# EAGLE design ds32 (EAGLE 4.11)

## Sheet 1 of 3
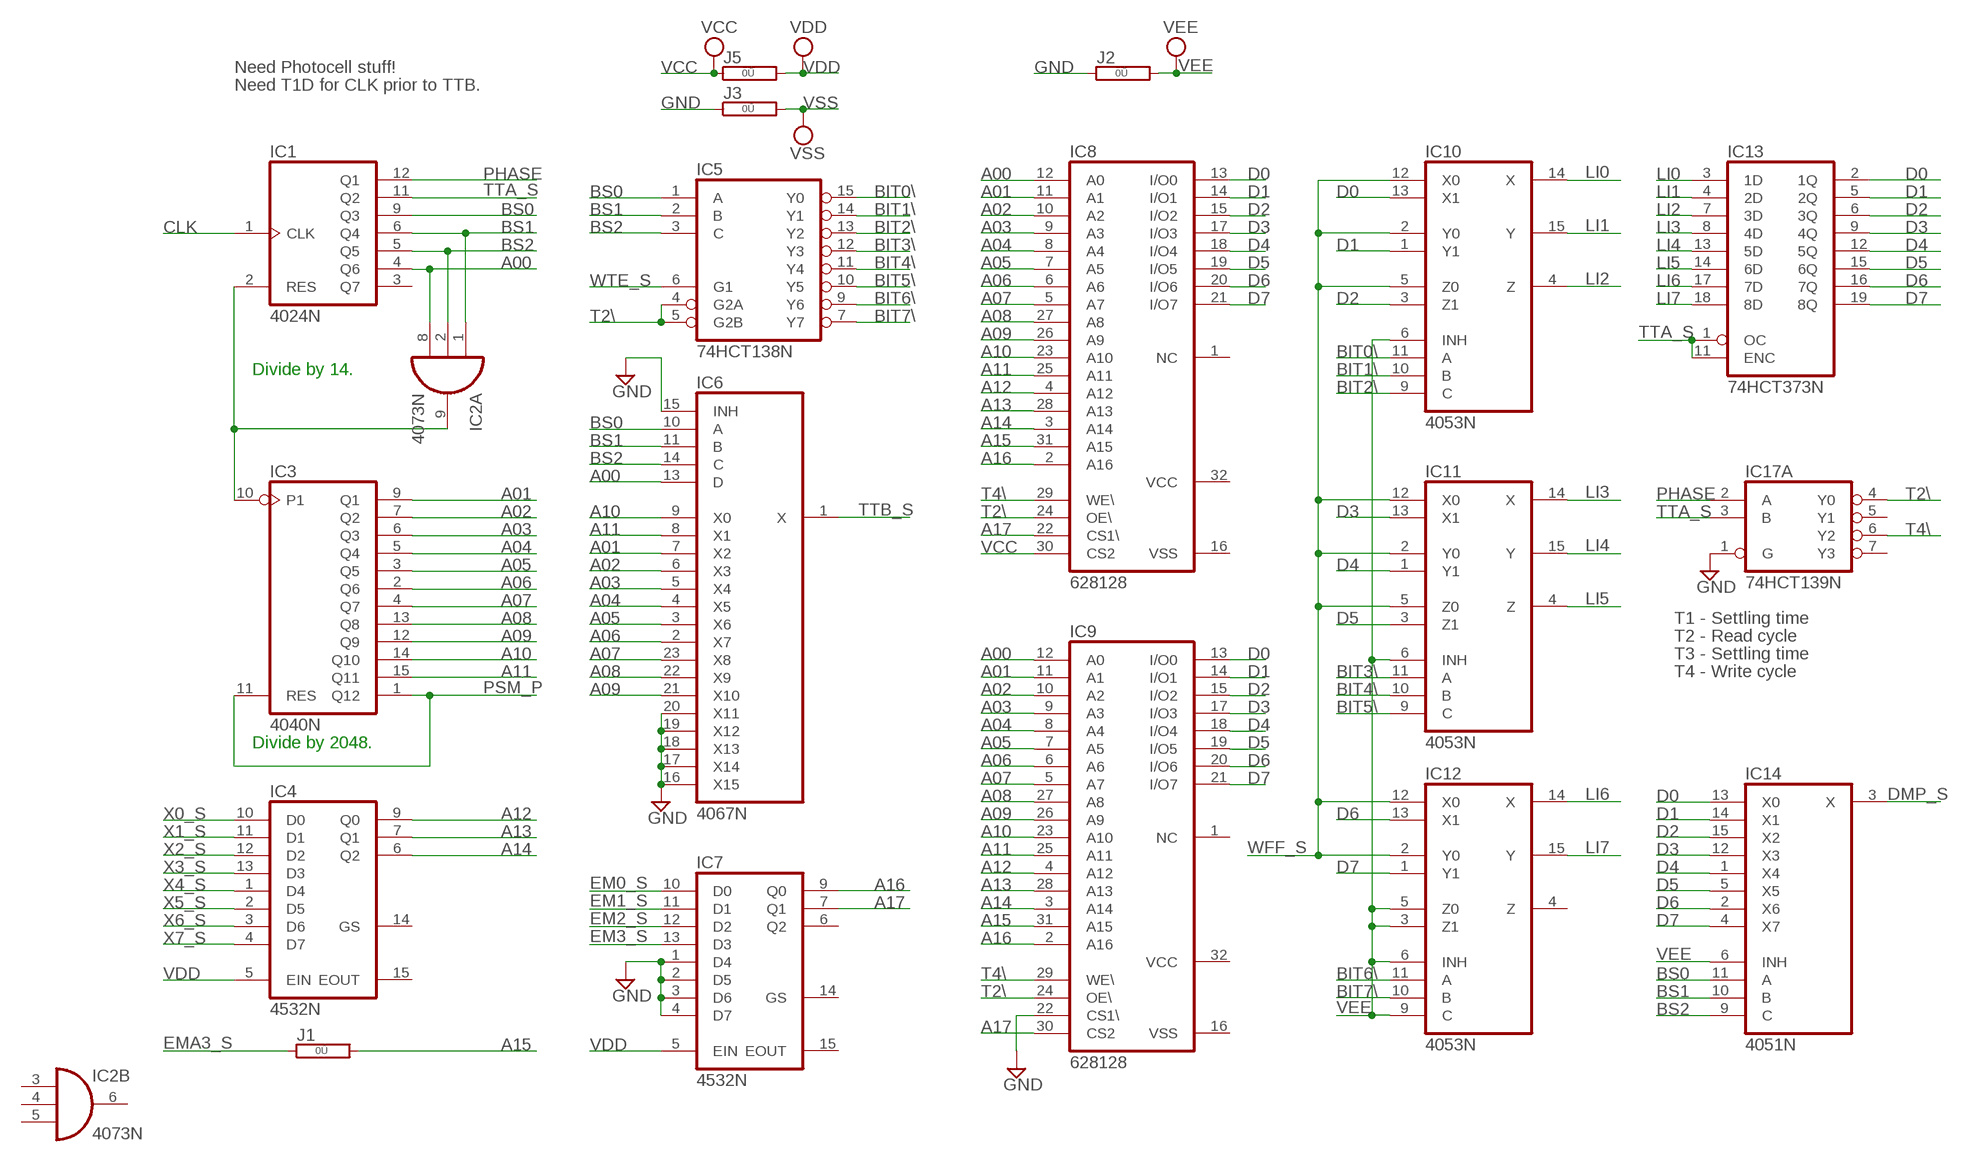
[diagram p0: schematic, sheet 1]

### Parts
IC1  4024N  [DIL14]
IC2  4073N  [DIL14]
IC3  4040N  [DIL16]
IC4  4532N  [DIL16]
IC5  74HCT138N  74LS138N  [DIL16]
IC6  4067N  [DIL24-6]
IC7  4532N  [DIL16]
IC8  628128  628128P  [DIL32]
IC9  628128  628128P  [DIL32]
IC10  4053N  [DIL16]
IC11  4053N  [DIL16]
IC12  4053N  [DIL16]
IC13  74HCT373N  74LS373N  [DIL20]
IC14  4051N  [DIL16]
IC17  74HCT139N  74LS139N  [DIL16]
J1  0R  [0R/10]
J2  0R  [0R/10]
J3  0R  [0R/10]
J5  0R  [0R/10]

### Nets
A00: IC1.4(Q6) IC2.8(A:I2) IC6.13(D) IC8.12(A0) IC9.12(A0)
A01: IC3.9(Q1) IC6.7(X2) IC8.11(A1) IC9.11(A1)
A02: IC3.7(Q2) IC6.6(X3) IC8.10(A2) IC9.10(A2)
A03: IC3.6(Q3) IC6.5(X4) IC8.9(A3) IC9.9(A3)
A04: IC3.5(Q4) IC6.4(X5) IC8.8(A4) IC9.8(A4)
A05: IC3.3(Q5) IC6.3(X6) IC8.7(A5) IC9.7(A5)
A06: IC3.2(Q6) IC6.2(X7) IC8.6(A6) IC9.6(A6)
A07: IC3.4(Q7) IC6.23(X8) IC8.5(A7) IC9.5(A7)
A08: IC3.13(Q8) IC6.22(X9) IC8.27(A8) IC9.27(A8)
A09: IC3.12(Q9) IC6.21(X10) IC8.26(A9) IC9.26(A9)
A10: IC3.14(Q10) IC6.9(X0) IC8.23(A10) IC9.23(A10)
A11: IC3.15(Q11) IC6.8(X1) IC8.25(A11) IC9.25(A11)
A12: IC4.9(Q0) IC8.4(A12) IC9.4(A12)
A13: IC4.7(Q1) IC8.28(A13) IC9.28(A13)
A14: IC4.6(Q2) IC8.3(A14) IC9.3(A14)
A15: IC8.31(A15) IC9.31(A15) J1.2
A16: IC7.9(Q0) IC8.2(A16) IC9.2(A16)
A17: IC7.7(Q1) IC8.22(CS1\) IC9.30(CS2)
BIT0\: IC5.15(Y0) IC10.11(A)
BIT1\: IC5.14(Y1) IC10.10(B)
BIT2\: IC5.13(Y2) IC10.9(C)
BIT3\: IC5.12(Y3) IC11.11(A)
BIT4\: IC5.11(Y4) IC11.10(B)
BIT5\: IC5.10(Y5) IC11.9(C)
BIT6\: IC5.9(Y6) IC12.11(A)
BIT7\: IC5.7(Y7) IC12.10(B)
BS0: IC1.9(Q3) IC5.1(A) IC6.10(A) IC14.11(A)
BS1: IC1.6(Q4) IC2.1(A:I0) IC5.2(B) IC6.11(B) IC14.10(B)
BS2: IC1.5(Q5) IC2.2(A:I1) IC5.3(C) IC6.14(C) IC14.9(C)
CLK: IC1.1(CLK) ; also sheet 3
D0: IC8.13(I/O0) IC9.13(I/O0) IC10.13(X1) IC13.2(1Q) IC14.13(X0)
D1: IC8.14(I/O1) IC9.14(I/O1) IC10.1(Y1) IC13.5(2Q) IC14.14(X1)
D2: IC8.15(I/O2) IC9.15(I/O2) IC10.3(Z1) IC13.6(3Q) IC14.15(X2)
D3: IC8.17(I/O3) IC9.17(I/O3) IC11.13(X1) IC13.9(4Q) IC14.12(X3)
D4: IC8.18(I/O4) IC9.18(I/O4) IC11.1(Y1) IC13.12(5Q) IC14.1(X4)
D5: IC8.19(I/O5) IC9.19(I/O5) IC11.3(Z1) IC13.15(6Q) IC14.5(X5)
D6: IC8.20(I/O6) IC9.20(I/O6) IC12.13(X1) IC13.16(7Q) IC14.2(X6)
D7: IC8.21(I/O7) IC9.21(I/O7) IC12.1(Y1) IC13.19(8Q) IC14.4(X7)
DMP_S: IC14.3(X) ; also sheet 2
EM0_S: IC7.10(D0) ; also sheet 2
EM1_S: IC7.11(D1) ; also sheet 2
EM2_S: IC7.12(D2) ; also sheet 2
EM3_S: IC7.13(D3) ; also sheet 2
EMA3_S: J1.1 ; also sheet 2
GND [Supply]: IC6.15(INH) IC6.16(X15) IC6.17(X14) IC6.18(X13) IC6.19(X12) IC6.20(X11) IC7.1(D4) IC7.2(D5) IC7.3(D6) IC7.4(D7) IC9.22(CS1\) IC17.1(A:G) J2.1 J3.1 ; also sheet 2,3
LI0: IC10.14(X) IC13.3(1D)
LI1: IC10.15(Y) IC13.4(2D)
LI2: IC10.4(Z) IC13.7(3D)
LI3: IC11.14(X) IC13.8(4D)
LI4: IC11.15(Y) IC13.13(5D)
LI5: IC11.4(Z) IC13.14(6D)
LI6: IC12.14(X) IC13.17(7D)
LI7: IC12.15(Y) IC13.18(8D)
N$1: IC1.2(RES) IC2.9(A:O) IC3.10(P1)
PHASE: IC1.12(Q1) IC17.2(A:A)
PSM_P: IC3.1(Q12) IC3.11(RES) ; also sheet 3
T2\: IC5.4(G2A) IC5.5(G2B) IC8.24(OE\) IC9.24(OE\) IC17.4(A:Y0)
T4\: IC8.29(WE\) IC9.29(WE\) IC17.6(A:Y2)
TTA_S: IC1.11(Q2) IC13.1(OC) IC13.11(ENC) IC17.3(A:B) ; also sheet 2
TTB_S: IC6.1(X) ; also sheet 2
VCC [Supply]: IC8.30(CS2) J5.1 ; also sheet 2,3
VDD [Supply]: IC4.5(EIN) IC7.5(EIN) J5.2
VEE: IC10.6(INH) IC11.6(INH) IC12.3(Z1) IC12.5(Z0) IC12.6(INH) IC12.9(C) IC14.6(INH) J2.2
VSS [Supply]: J3.2
WFF_S: IC10.2(Y0) IC10.5(Z0) IC10.12(X0) IC11.2(Y0) IC11.5(Z0) IC11.12(X0) IC12.2(Y0) IC12.12(X0) ; also sheet 2
WTE_S: IC5.6(G1) ; also sheet 2
X0_S: IC4.10(D0) ; also sheet 2
X1_S: IC4.11(D1) ; also sheet 2
X2_S: IC4.12(D2) ; also sheet 2
X3_S: IC4.13(D3) ; also sheet 2
X4_S: IC4.1(D4) ; also sheet 2
X5_S: IC4.2(D5) ; also sheet 2
X6_S: IC4.3(D6) ; also sheet 2
X7_S: IC4.4(D7) ; also sheet 2
Unconnected: IC1.3(Q7) IC2.10(C:O) IC2.11(C:I0) IC2.12(C:I1) IC2.13(C:I2) IC4.14(GS) IC4.15(EOUT) IC7.6(Q2) IC7.14(GS) IC7.15(EOUT) IC8.1(NC) IC9.1(NC) IC12.4(Z) IC17.5(A:Y1) IC17.7(A:Y3) IC17.9(B:Y3) IC17.10(B:Y2) IC17.11(B:Y1) IC17.12(B:Y0) IC17.13(B:B) IC17.14(B:A) IC17.15(B:G)

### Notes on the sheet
- Need Photocell stuff!
- Need T1D for CLK prior to TTB.
- Divide by 14.
- T1 - Settling time
- T2 - Read cycle
- T3 - Settling time
- T4 - Write cycle
- Divide by 2048.

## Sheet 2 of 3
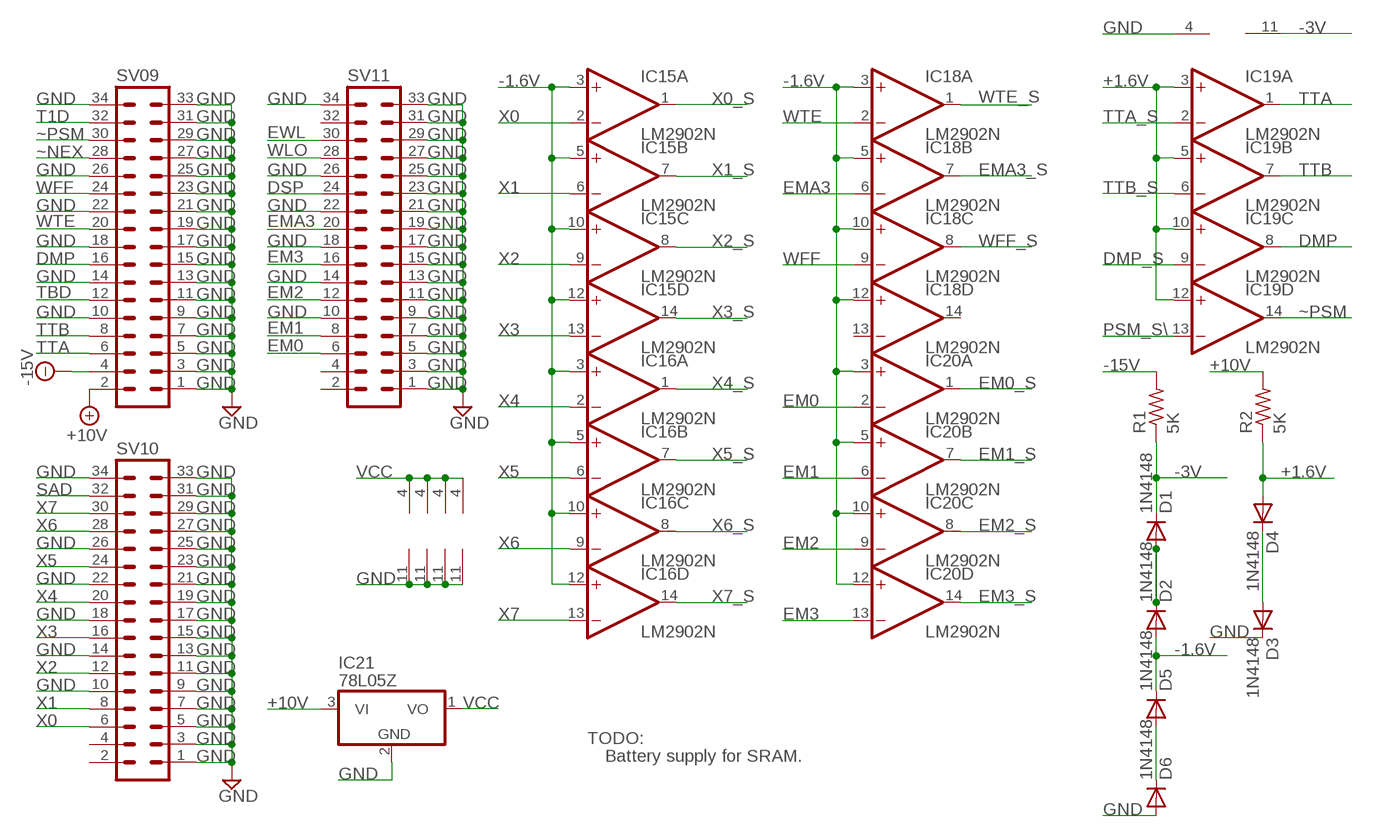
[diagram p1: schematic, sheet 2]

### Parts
D1  1N4148  [DO35-10]
D2  1N4148  [DO35-10]
D3  1N4148  [DO35-10]
D4  1N4148  [DO35-10]
D5  1N4148  [DO35-10]
D6  1N4148  [DO35-10]
IC15  LM2902N  [DIL14]
IC16  LM2902N  [DIL14]
IC18  LM2902N  [DIL14]
IC19  LM2902N  [DIL14]
IC20  LM2902N  [DIL14]
IC21  78L05Z  [TO92]
R1  5K  R-US_0207/10  [0207/10]
R2  5K  R-US_0207/10  [0207/10]
SV09  MA17-2  [MA17-2]
SV10  MA17-2  [MA17-2]
SV11  MA17-2  [MA17-2]

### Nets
+1.6V [Supply]: D4.A IC19.3(A:+IN) IC19.5(B:+IN) IC19.10(C:+IN) IC19.12(D:+IN) R2.1
+10V: IC21.3(VI) R2.2 SV09.2
-1.6V [Supply]: D2.A D5.C IC15.3(A:+IN) IC15.5(B:+IN) IC15.10(C:+IN) IC15.12(D:+IN) IC16.3(A:+IN) IC16.5(B:+IN) IC16.10(C:+IN) IC16.12(D:+IN) IC18.3(A:+IN) IC18.5(B:+IN) IC18.10(C:+IN) IC18.12(D:+IN) IC20.3(A:+IN) IC20.5(B:+IN) IC20.10(C:+IN) IC20.12(D:+IN)
-3V [Supply]: D1.C IC19.11(P:V-) R1.1 ; also sheet 3
-15V: R1.2 SV09.4
DMP: IC19.8(C:OUT) SV09.16
DMP_S: IC19.9(C:-IN) ; also sheet 1
DSP: SV11.24
EM0: IC20.2(A:-IN) SV11.6
EM0_S: IC20.1(A:OUT) ; also sheet 1
EM1: IC20.6(B:-IN) SV11.8
EM1_S: IC20.7(B:OUT) ; also sheet 1
EM2: IC20.9(C:-IN) SV11.12
EM2_S: IC20.8(C:OUT) ; also sheet 1
EM3: IC20.13(D:-IN) SV11.16
EM3_S: IC20.14(D:OUT) ; also sheet 1
EMA3: IC18.6(B:-IN) SV11.20
EMA3_S: IC18.7(B:OUT) ; also sheet 1
EWL: SV11.30
GND [Supply]: D3.C D6.A IC15.11(P:V-) IC16.11(P:V-) IC18.11(P:V-) IC19.4(P:V+) IC20.11(P:V-) IC21.2(GND) SV09.1 SV09.3 SV09.5 SV09.7 SV09.9 SV09.10 SV09.11 SV09.13 SV09.14 SV09.15 SV09.17 SV09.18 SV09.19 SV09.21 SV09.22 SV09.23 SV09.25 SV09.26 SV09.27 SV09.29 SV09.31 SV09.33 SV09.34 SV10.1 SV10.3 SV10.5 SV10.7 SV10.9 SV10.10 SV10.11 SV10.13 SV10.14 SV10.15 SV10.17 SV10.18 SV10.19 SV10.21 SV10.22 SV10.23 SV10.25 SV10.26 SV10.27 SV10.29 SV10.31 SV10.33 SV10.34 SV11.1 SV11.3 SV11.5 SV11.7 SV11.9 SV11.10 SV11.11 SV11.13 SV11.14 SV11.15 SV11.17 SV11.18 SV11.19 SV11.21 SV11.22 SV11.23 SV11.25 SV11.26 SV11.27 SV11.29 SV11.31 SV11.33 SV11.34 ; also sheet 1,3
N$2: D1.A D2.C
N$3: D3.A D4.C
N$5: D5.A D6.C
PSM_S\: IC19.13(D:-IN) ; also sheet 3
SAD: SV10.32
T1D: SV09.32
TBD: SV09.12
TTA: IC19.1(A:OUT) SV09.6
TTA_S: IC19.2(A:-IN) ; also sheet 1
TTB: IC19.7(B:OUT) SV09.8
TTB_S: IC19.6(B:-IN) ; also sheet 1
VCC [Supply]: IC15.4(P:V+) IC16.4(P:V+) IC18.4(P:V+) IC20.4(P:V+) IC21.1(VO) ; also sheet 1,3
WFF: IC18.9(C:-IN) SV09.24
WFF_S: IC18.8(C:OUT) ; also sheet 1
WLO: SV11.28 ; also sheet 3
WTE: IC18.2(A:-IN) SV09.20
WTE_S: IC18.1(A:OUT) ; also sheet 1
X0: IC15.2(A:-IN) SV10.6
X0_S: IC15.1(A:OUT) ; also sheet 1
X1: IC15.6(B:-IN) SV10.8
X1_S: IC15.7(B:OUT) ; also sheet 1
X2: IC15.9(C:-IN) SV10.12
X2_S: IC15.8(C:OUT) ; also sheet 1
X3: IC15.13(D:-IN) SV10.16
X3_S: IC15.14(D:OUT) ; also sheet 1
X4: IC16.2(A:-IN) SV10.20
X4_S: IC16.1(A:OUT) ; also sheet 1
X5: IC16.6(B:-IN) SV10.24
X5_S: IC16.7(B:OUT) ; also sheet 1
X6: IC16.9(C:-IN) SV10.28
X6_S: IC16.8(C:OUT) ; also sheet 1
X7: IC16.13(D:-IN) SV10.30
X7_S: IC16.14(D:OUT) ; also sheet 1
~NEX: SV09.28 ; also sheet 3
~PSM: IC19.14(D:OUT) SV09.30
Unconnected: IC18.13(D:-IN) IC18.14(D:OUT) SV10.2 SV10.4 SV11.2 SV11.4 SV11.32

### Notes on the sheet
- TODO:
- Battery supply for SRAM.

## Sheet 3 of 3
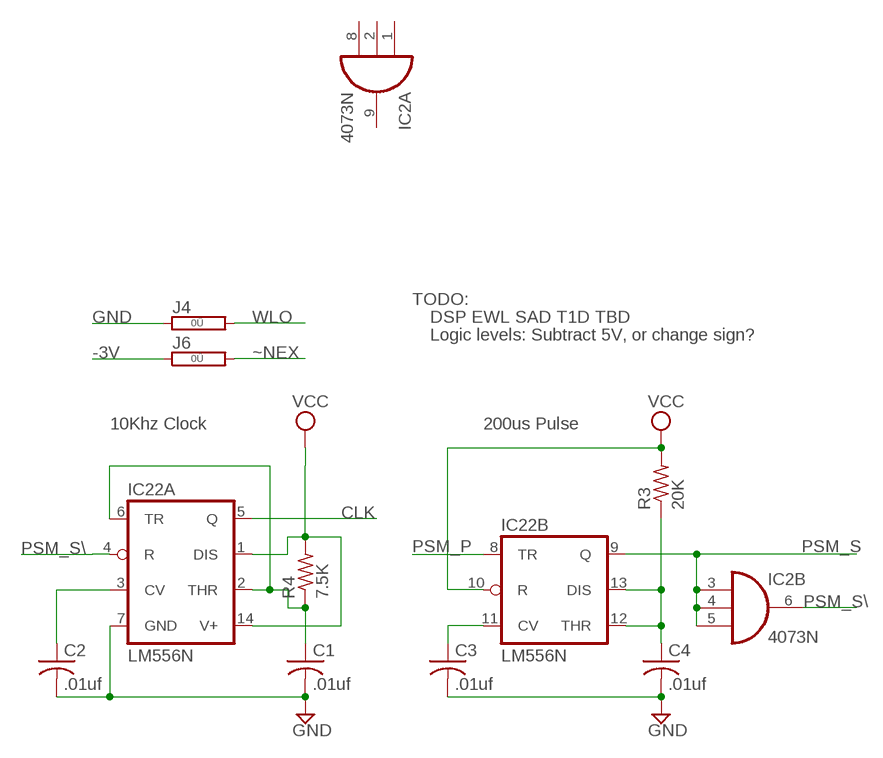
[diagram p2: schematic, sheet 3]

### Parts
C1  .01uf  C-US050-025X075  [C050-025X075]
C2  .01uf  C-US050-025X075  [C050-025X075]
C3  .01uf  C-US050-025X075  [C050-025X075]
C4  .01uf  C-US050-025X075  [C050-025X075]
IC22  LM556N  [DIL14]
J4  0R  [0R/10]
J6  0R  [0R/10]
R3  20K  R-US_0207/10  [0207/10]
R4  7.5K  R-US_0207/10  [0207/10]

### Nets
-3V [Supply]: J6.1 ; also sheet 2
CLK: IC22.5(A:Q) ; also sheet 1
GND [Supply]: C1.2 C2.2 C3.2 C4.2 IC22.7(A:GND) J4.1 ; also sheet 1,2
N$6: C1.1 IC22.2(A:THR) IC22.6(A:TR) R4.1
N$7: C2.1 IC22.3(A:CV)
N$8: C4.1 IC22.12(B:THR) IC22.13(B:DIS) R3.1
N$10: C3.1 IC22.11(B:CV)
PSM_P: IC22.8(B:TR) ; also sheet 1
PSM_S: IC2.3(B:I0) IC2.4(B:I1) IC2.5(B:I2) IC22.9(B:Q)
PSM_S\: IC2.6(B:O) IC22.4(A:R) ; also sheet 2
VCC [Supply]: IC22.1(A:DIS) IC22.10(B:R) IC22.14(A:V+) R3.2 R4.2 ; also sheet 1,2
WLO: J4.2 ; also sheet 2
~NEX: J6.2 ; also sheet 2

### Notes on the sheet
- TODO:
- DSP EWL SAD T1D TBD
- Logic levels: Subtract 5V, or change sign?
- 10Khz Clock | 200us Pulse

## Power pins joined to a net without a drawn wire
GND: IC5.8(GND) IC10.8(GND) IC11.8(GND) IC12.8(GND) IC13.10(GND) IC14.8(GND) IC17.8(P:GND)
VCC: IC5.16(VCC) IC8.32(VCC) IC9.32(VCC) IC10.16(VCC) IC11.16(VCC) IC12.16(VCC) IC13.20(VCC) IC14.16(VCC) IC17.16(P:VCC)
VDD: IC1.14(VDD) IC2.14(P:VDD) IC3.16(VDD) IC4.16(VDD) IC6.24(VDD) IC7.16(VDD)
VEE: IC10.7(VEE) IC11.7(VEE) IC12.7(VEE) IC14.7(VEE)
VSS: IC1.7(VSS) IC2.7(P:VSS) IC3.8(VSS) IC4.8(VSS) IC6.12(VSS) IC7.8(VSS) IC8.16(VSS) IC9.16(VSS)

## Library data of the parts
C1-C4 = rcl:C-US: CAPACITOR, American symbol
D1-D6 = diode:1N4148: DIODE
IC1 = 40xx:4024: 7-stage binary/ripple COUNTER
IC2 = 40xx:4073: Triple 3-input AND
IC3 = 40xx:4040: 12-stage binary/ripple COUNTER
IC4 IC7 = 45xx:4532: 8-bit PRIORITY ENCODER
IC5 = 74xx-us:74*138: 3-line to 8-line DECODER/DEMULTIPLEXER
IC6 = 40xx:4067: 16-channel ANALOG MULTIPLEXER
IC8 IC9 = memory-hitachi:628128P: MEMORY
IC10-IC12 = 40xx:4053: Triple 2-channel ANALOG MULTIPLEXER
IC13 = 74xx-us:74*373: Octal D type transparent LATCH, edge triggered
IC14 = 40xx:4051: 8-channel ANALOG MULTIPLEXER
IC15 IC16 IC18-IC20 = linear:LM2902: COMPARATOR
IC17 = 74xx-us:74*139: Dual 2-line to 4-line DECODER/DEMULTIPLEXER
IC21 = linear:78*: Positive VOLTAGE REGULATOR
IC22 = linear:*556: Dual TIMER
J1-J6 = jumper:0R: Bridge 0R 10mm
R1-R4 = rcl:R-US_: RESISTOR, American symbol
SV09 SV10 SV11 = con-lstb:MA17-2: PIN HEADER

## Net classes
1 Supply: width 0.381 mm

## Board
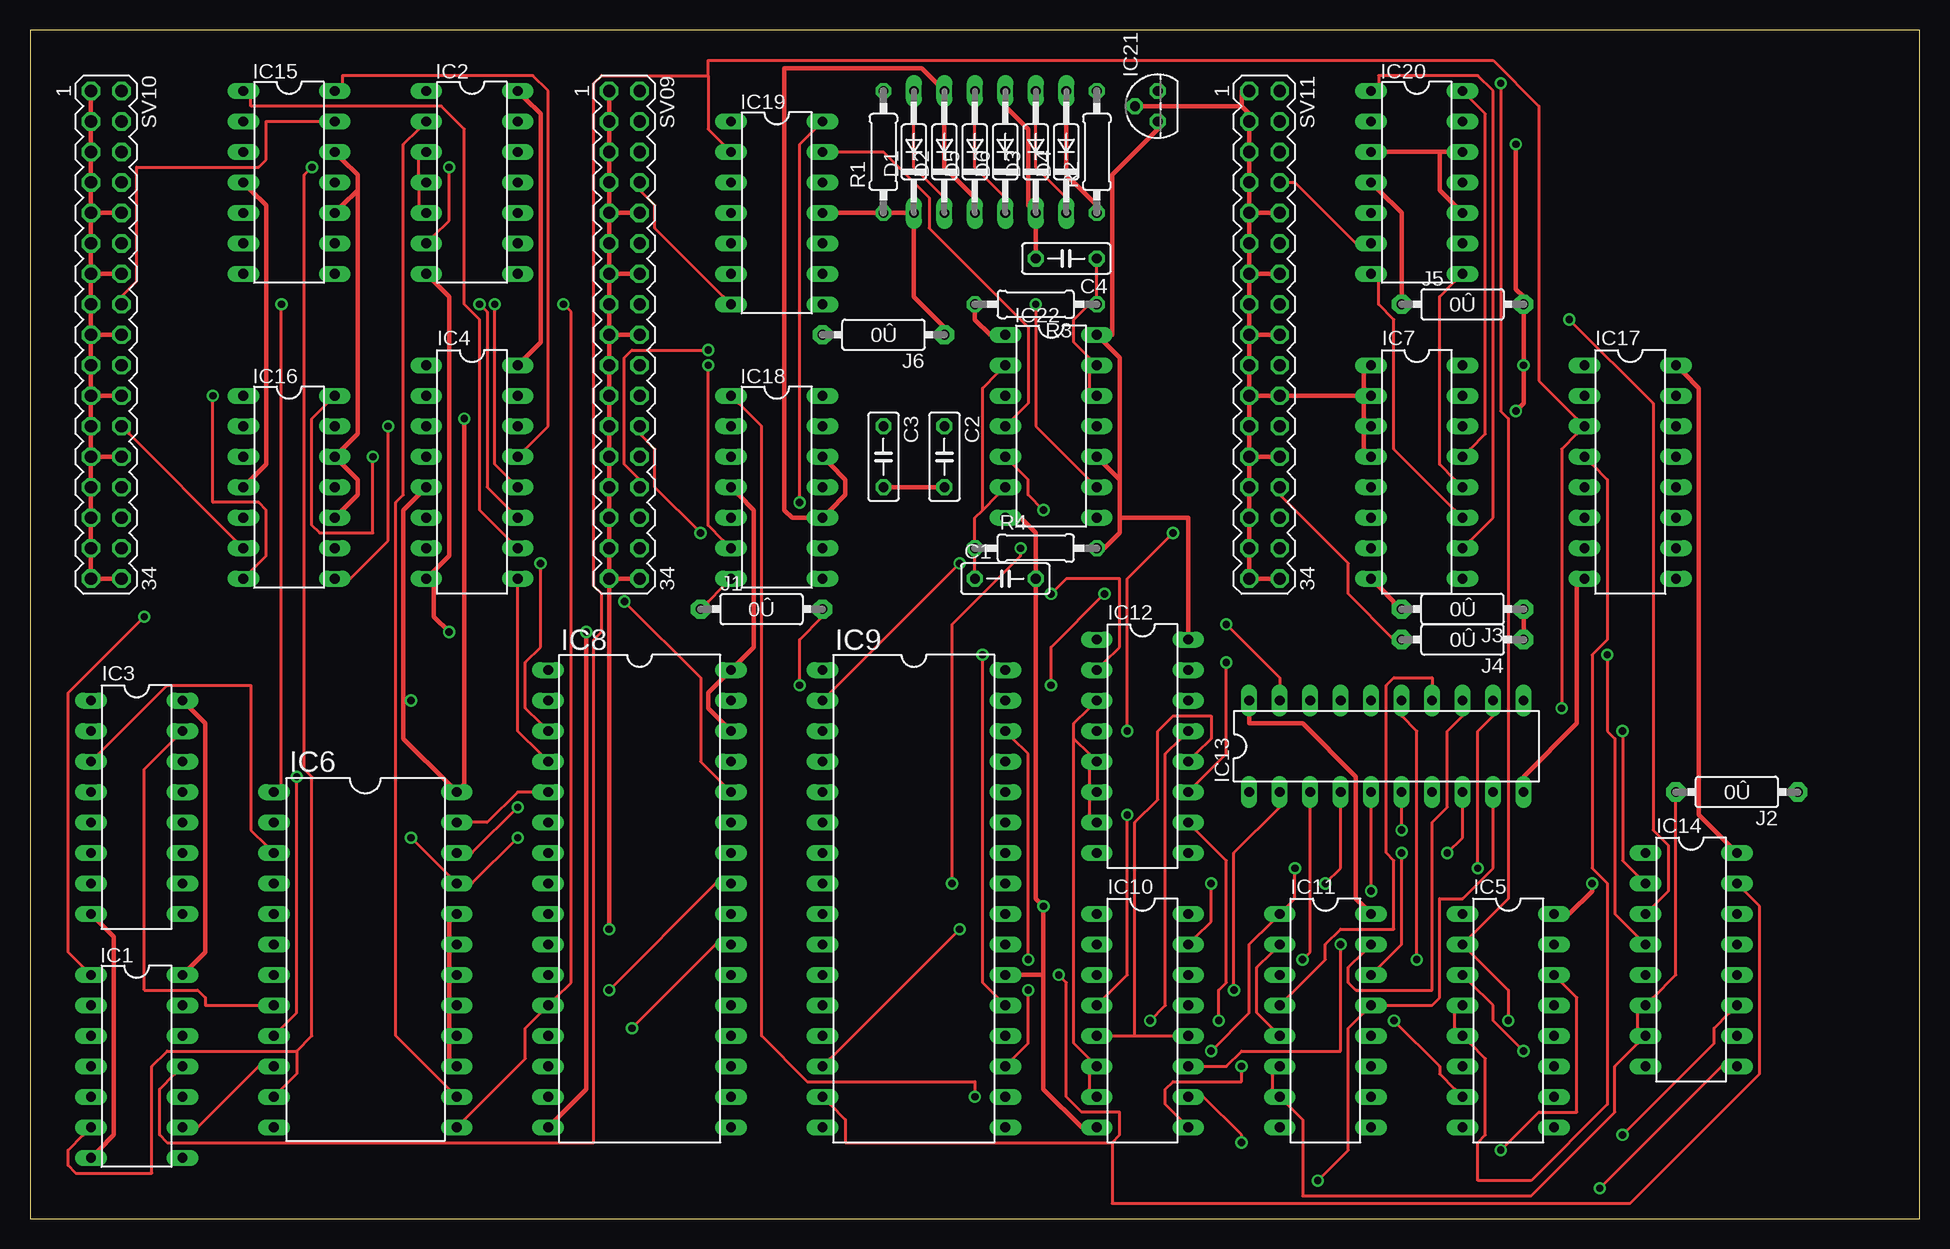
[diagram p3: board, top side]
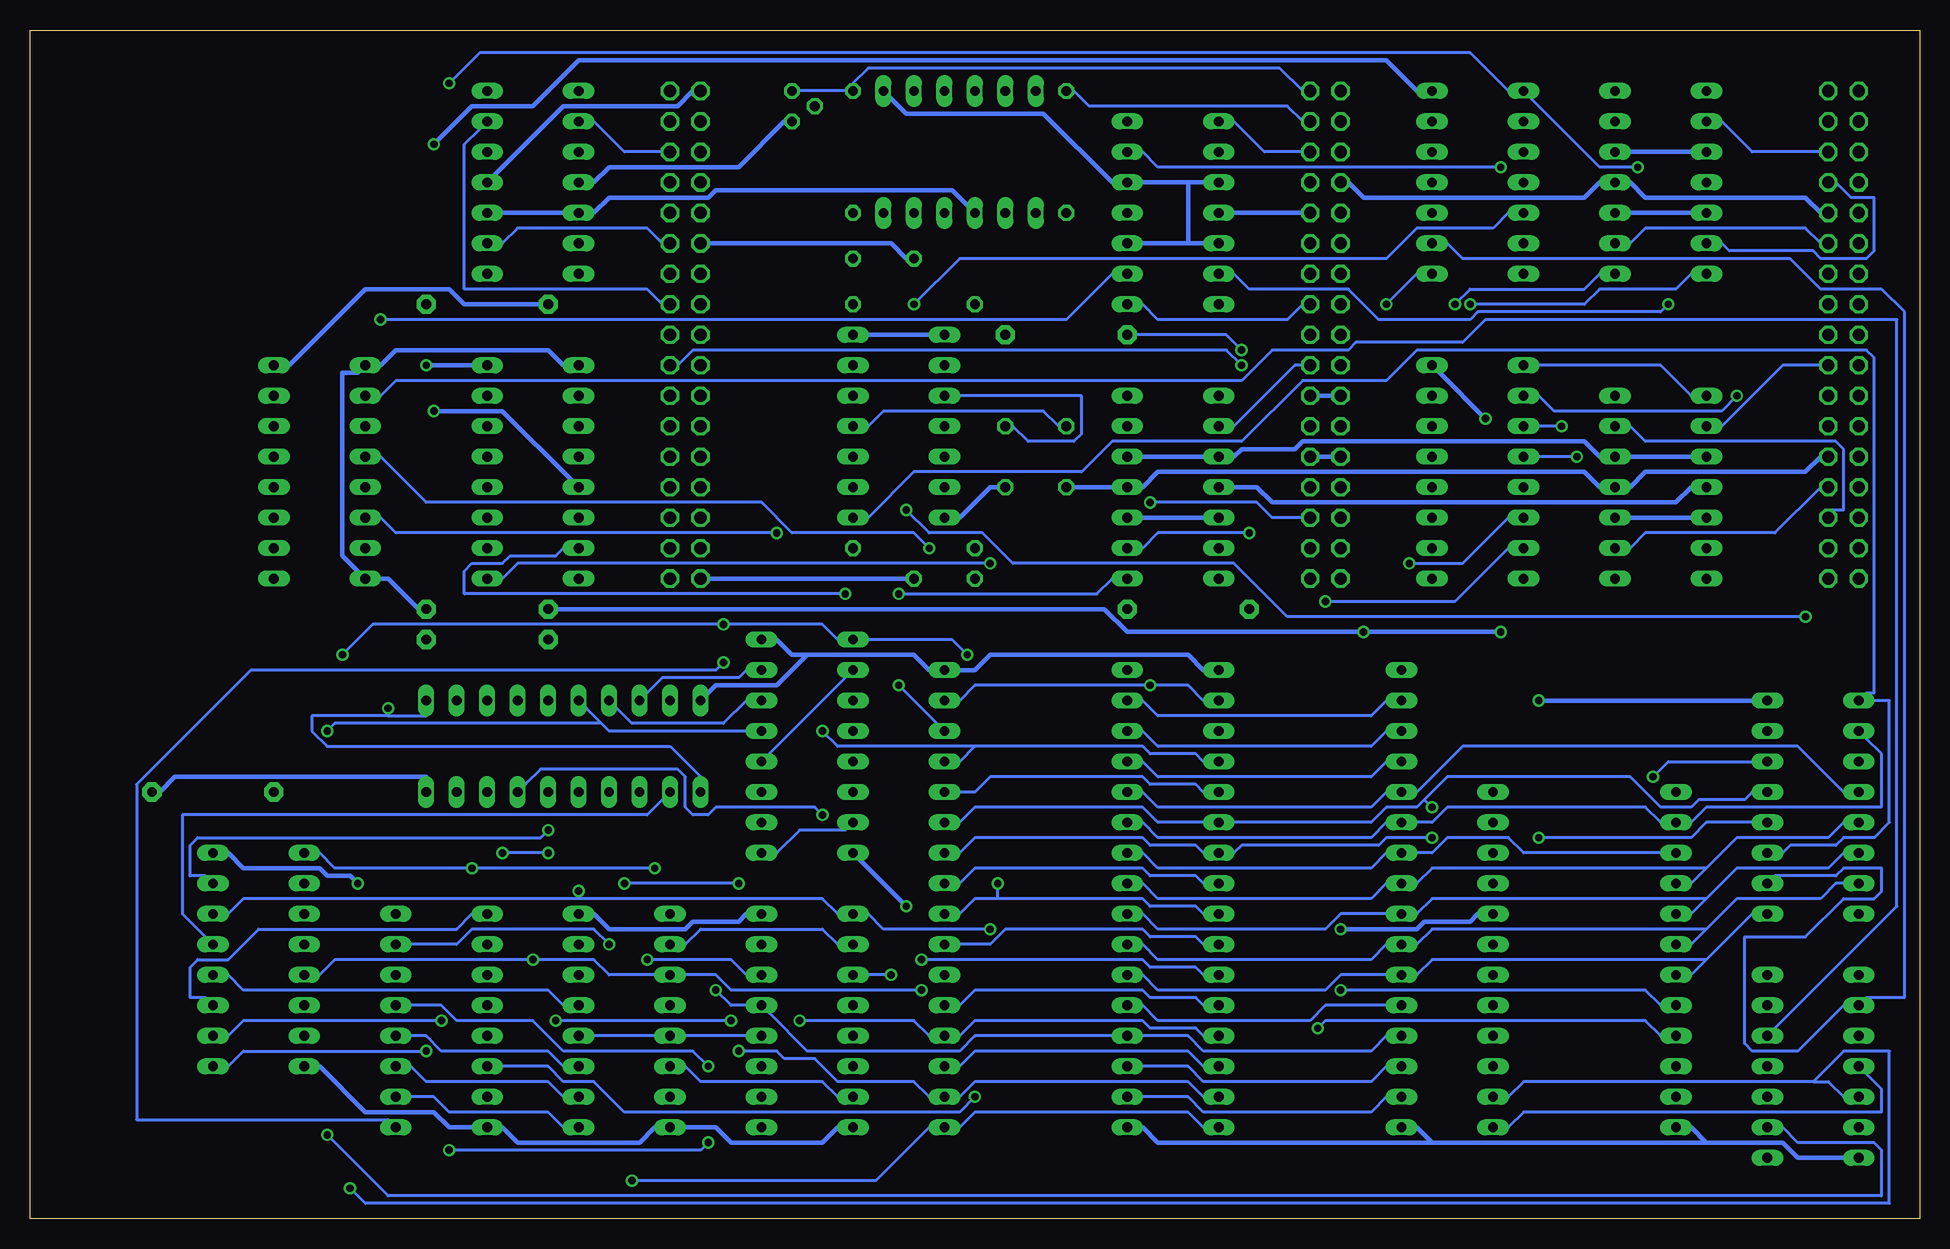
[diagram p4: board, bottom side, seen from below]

Size 157.48 x 99.06 mm. Coordinates in mm from the lower left corner, seen from the top.
Outline: 0,0 157.48,0 157.48,99.06 0,99.06 0,0
Copper layers (1*16): Top 0.035mm / dielectric 1.5mm / Bottom 0.035mm
Design rules "10mils": minimum track width 10mil, minimum drill 24mil, track to track 10mil, track to pad 10mil, pad to pad 10mil, via to via 10mil, smd to smd 10mil, copper to edge 40mil, drill to drill 10mil, minimum pad ring 10mil, minimum via ring 8mil, stop-mask expansion 0mil, vias tented up to drill 0mil, thermal gap 10mil

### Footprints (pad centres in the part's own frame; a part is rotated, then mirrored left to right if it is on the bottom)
C050-025X075 = drill 0.813 octagon: 1 -2.54,0; 2 2.54,0
DO35-10 = drill 0.813 long: A 5.08,0; C -5.08,0
DIL14 = drill 0.813 long: 1 -7.62,-3.81; 2 -5.08,-3.81; 3 -2.54,-3.81; 4 0,-3.81; 5 2.54,-3.81; 6 5.08,-3.81; 7 7.62,-3.81; 8 7.62,3.81; 9 5.08,3.81; 10 2.54,3.81; 11 0,3.81; 12 -2.54,3.81; 13 -5.08,3.81; 14 -7.62,3.81
DIL16 = drill 0.813 long: 1 -8.89,-3.81; 2 -6.35,-3.81; 3 -3.81,-3.81; 4 -1.27,-3.81; 5 1.27,-3.81; 6 3.81,-3.81; 7 6.35,-3.81; 8 8.89,-3.81; 9 8.89,3.81; 10 6.35,3.81; 11 3.81,3.81; 12 1.27,3.81; 13 -1.27,3.81; 14 -3.81,3.81; 15 -6.35,3.81; 16 -8.89,3.81
DIL24-6 = drill 0.813 long: 1 -13.97,-7.62; 2 -11.43,-7.62; 3 -8.89,-7.62; 4 -6.35,-7.62; 5 -3.81,-7.62; 6 -1.27,-7.62; 7 1.27,-7.62; 8 3.81,-7.62; 9 6.35,-7.62; 10 8.89,-7.62; 11 11.43,-7.62; 12 13.97,-7.62; 13 13.97,7.62; 14 11.43,7.62; 15 8.89,7.62; 16 6.35,7.62; 17 3.81,7.62; 18 1.27,7.62; 19 -1.27,7.62; 20 -3.81,7.62; 21 -6.35,7.62; 22 -8.89,7.62; 23 -11.43,7.62; 24 -13.97,7.62
DIL32 = drill 0.813 long: 1 -19.05,-7.62; 2 -16.51,-7.62; 3 -13.97,-7.62; 4 -11.43,-7.62; 5 -8.89,-7.62; 6 -6.35,-7.62; 7 -3.81,-7.62; 8 -1.27,-7.62; 9 1.27,-7.62; 10 3.81,-7.62; 11 6.35,-7.62; 12 8.89,-7.62; 13 11.43,-7.62; 14 13.97,-7.62; 15 16.51,-7.62; 16 19.05,-7.62; 17 19.05,7.62; 18 16.51,7.62; 19 13.97,7.62; 20 11.43,7.62; 21 8.89,7.62; 22 6.35,7.62; 23 3.81,7.62; 24 1.27,7.62; 25 -1.27,7.62; 26 -3.81,7.62; 27 -6.35,7.62; 28 -8.89,7.62; 29 -11.43,7.62; 30 -13.97,7.62; 31 -16.51,7.62; 32 -19.05,7.62
DIL20 = drill 0.813 long: 1 -11.43,-3.81; 2 -8.89,-3.81; 3 -6.35,-3.81; 4 -3.81,-3.81; 5 -1.27,-3.81; 6 1.27,-3.81; 7 3.81,-3.81; 8 6.35,-3.81; 9 8.89,-3.81; 10 11.43,-3.81; 11 11.43,3.81; 12 8.89,3.81; 13 6.35,3.81; 14 3.81,3.81; 15 1.27,3.81; 16 -1.27,3.81; 17 -3.81,3.81; 18 -6.35,3.81; 19 -8.89,3.81; 20 -11.43,3.81
TO92 = drill 0.813 octagon: 1 -1.27,0; 2 0,1.905; 3 1.27,0
0R/10 = drill 0.813 pad 1.6 octagon: 1 -5.08,0; 2 5.08,0
0207/10 = drill 0.813 octagon: 1 -5.08,0; 2 5.08,0
MA17-2 = drill 1.016 octagon: 1 -20.32,-1.27; 2 -20.32,1.27; 3 -17.78,-1.27; 4 -17.78,1.27; 5 -15.24,-1.27; 6 -15.24,1.27; 7 -12.7,-1.27; 8 -12.7,1.27; 9 -10.16,-1.27; 10 -10.16,1.27; 11 -7.62,-1.27; 12 -7.62,1.27; 13 -5.08,-1.27; 14 -5.08,1.27; 15 -2.54,-1.27; 16 -2.54,1.27; 17 0,-1.27; 18 0,1.27; 19 2.54,-1.27; 20 2.54,1.27; 21 5.08,-1.27; 22 5.08,1.27; 23 7.62,-1.27; 24 7.62,1.27; 25 10.16,-1.27; 26 10.16,1.27; 27 12.7,-1.27; 28 12.7,1.27; 29 15.24,-1.27; 30 15.24,1.27; 31 17.78,-1.27; 32 17.78,1.27; 33 20.32,-1.27; 34 20.32,1.27

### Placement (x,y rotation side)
C1  81.28,53.34 0 top
C2  76.2,63.5 270 top
C3  71.12,63.5 270 top
C4  86.36,80.01 180 top
D1  73.66,88.9 90 top
D2  76.2,88.9 90 top
D3  83.82,88.9 90 top
D4  86.36,88.9 90 top
D5  78.74,88.9 90 top
D6  81.28,88.9 90 top
IC1  8.89,12.7 270 top
IC2  36.83,86.36 270 top
IC3  8.89,34.29 270 top
IC4  36.83,62.23 270 top
IC5  123.19,16.51 270 top
IC6  27.94,21.59 270 top
IC7  115.57,62.23 270 top
IC8  50.8,26.67 270 top
IC9  73.66,26.67 270 top
IC10  92.71,16.51 270 top
IC11  107.95,16.51 270 top
IC12  92.71,39.37 270 top
IC13  113.03,39.37 0 top
IC14  138.43,21.59 270 top
IC15  21.59,86.36 270 top
IC16  21.59,60.96 270 top
IC17  133.35,62.23 270 top
IC18  62.23,60.96 270 top
IC19  62.23,83.82 270 top
IC20  115.57,86.36 270 top
IC21  93.98,92.71 90 top
IC22  85.09,66.04 270 top
J1  60.96,50.8 0 top
J2  142.24,35.56 180 top
J3  119.38,50.8 180 top
J4  119.38,48.26 180 top
J5  119.38,76.2 0 top
J6  71.12,73.66 180 top
R1  71.12,88.9 90 top
R2  88.9,88.9 90 top
R3  83.82,76.2 180 top
R4  83.82,55.88 0 top
SV09  49.53,73.66 270 top
SV10  6.35,73.66 270 top
SV11  102.87,73.66 270 top

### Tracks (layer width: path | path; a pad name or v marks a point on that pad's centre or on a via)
+1.6V
  Top 0.381: R2.1 88.9,84.45 86.36,87 86.36,92.71 D4.A
  Bottom 0.381: 60.96,81.28 64.77,81.28 IC19.10 | 60.96,81.28 59.69,81.28 IC19.5 | 60.96,86.36 64.77,86.36 IC19.12 67.31,86.36 73.03,92.08 84.45,92.08 85.72,93.34 D4.A | 60.96,86.36 59.69,86.36 IC19.3 | 60.96,81.28 60.96,86.36
+10V
  Bottom 0.254: IC21.3 93.34,93.98 89.53,93.98 R2.2 88.9,94.61 87.63,95.89 53.34,95.89 51.44,93.98 SV09.2
-1.6V
  Top 0.381: D5.C 78.74,85.09 76.2,87.63 76.2,92.71 D2.A 75.56,94.61 74.3,95.89 62.87,95.89 62.87,59.05 63.5,58.42 64.77,58.42 IC18.10 66.67,59.05 67.94,60.33 67.94,61.59 66.67,62.87 IC18.12 | 117.47,88.9 118.11,88.9 IC20.12 | 117.47,88.9 113.03,88.9 IC20.3 | 117.47,88.9 117.47,85.72 118.75,84.45 IC20.10 | IC16.10 26.04,59.05 27.3,60.33 27.3,61.59 26.04,62.87 IC16.12 26.04,64.14 27.3,65.41 27.3,85.72 | 27.3,85.72 26.04,84.45 IC15.10 | 27.3,85.72 27.3,87 26.04,88.27 IC15.12
  Bottom 0.381: IC20.10 118.11,83.82 113.03,83.82 IC20.5 110.49,83.82 109.22,85.09 100.97,85.09 100.33,85.72 80.64,85.72 79.38,84.45 D5.C | IC18.5 59.69,58.42 64.77,58.42 IC18.10 | IC18.12 64.77,63.5 59.69,63.5 IC18.3 57.15,63.5 56.52,64.14 52.07,64.14 51.44,64.77 27.94,64.77 26.67,63.5 IC16.12 24.13,63.5 19.05,63.5 IC16.3 | IC16.5 19.05,58.42 24.13,58.42 IC16.10 | IC15.5 19.05,83.82 24.13,83.82 IC15.10 | IC15.3 19.05,88.9 24.13,88.9 IC15.12
-3V
  Top 0.381: IC19.11 67.31,83.82 70.48,83.82 R1.1 71.75,83.82 73.03,83.82 D1.C 73.66,82.55 73.66,76.83 76.2,74.3 J6.1
-15V
  Bottom 0.254: R1.2 70.48,93.98 69.22,92.71 52.7,92.71 51.44,91.44 SV09.4
A00  (via drill 0.61)
  Top 0.254: IC6.13 36.2,8.26 41.27,13.34 41.27,15.88 42.55,17.14 IC8.12 43.81,18.41 45.09,19.68 45.09,75.56 v44.45,76.2
  Bottom 0.254: IC1.4 4.45,12.06 3.17,10.79 3.17,8.89 33.02,8.89 34.29,7.62 IC6.13 | IC9.12 64.77,17.78 63.5,16.51 50.8,16.51 49.53,17.78 44.45,17.78 IC8.12 | v44.45,76.2 41.91,78.74 IC2.8
A01
  Bottom 0.254: 17.78,21.59 13.97,25.4 IC3.9 | 17.78,21.59 19.05,20.32 IC6.7 | 17.78,21.59 40.64,21.59 41.91,20.32 IC8.11 44.45,20.32 48.26,20.32 49.53,19.05 63.5,19.05 64.77,20.32 IC9.11
A02
  Bottom 0.254: 17.78,24.13 15.24,26.67 8.26,26.67 6.99,27.94 6.35,27.94 IC3.7 | 17.78,24.13 19.05,22.86 IC6.6 | 17.78,24.13 40.64,24.13 41.91,22.86 IC8.10 44.45,22.86 45.72,21.59 63.5,21.59 64.77,22.86 IC9.10
A03
  Bottom 0.254: 17.78,26.67 15.24,29.21 7.62,29.21 6.35,30.48 IC3.6 | 17.78,26.67 19.05,25.4 IC6.5 | 17.78,26.67 40.64,26.67 41.91,25.4 IC8.9 44.45,25.4 48.26,25.4 49.53,24.13 63.5,24.13 64.77,25.4 IC9.9
A04
  Bottom 0.254: 17.78,29.21 15.24,31.75 7.62,31.75 6.35,33.02 IC3.5 | 17.78,29.21 19.05,27.94 IC6.4 | 17.78,29.21 40.64,29.21 41.91,27.94 IC8.8 44.45,27.94 45.72,26.67 63.5,26.67 64.77,27.94 IC9.8
A05
  Top 0.254: IC3.3 5.71,38.73 11.43,44.45 18.41,44.45 18.41,32.38 19.68,31.11 IC6.3
  Bottom 0.254: IC6.3 21.59,30.48 33.02,30.48 34.29,31.75 39.37,31.75 40.64,30.48 41.91,30.48 IC8.7 44.45,30.48 45.72,29.21 63.5,29.21 64.77,30.48 IC9.7
A06
  Bottom 0.254: IC9.6 64.77,33.02 63.5,31.75 45.72,31.75 44.45,33.02 IC8.6 41.91,33.02 40.64,33.02 39.37,34.29 22.86,34.29 21.59,33.02 IC6.2 19.05,33.02 17.78,34.29 3.17,34.29 3.17,38.73 4.45,40.01 IC3.2
A07
  Top 0.254: IC6.23 36.83,33.02 38.1,33.02 40.64,35.56 41.91,35.56 IC8.5
  Bottom 0.254: IC3.4 6.35,35.56 10.16,39.37 38.1,39.37 41.91,35.56 IC8.5 44.45,35.56 45.72,34.29 63.5,34.29 64.77,35.56 IC9.5
A08  (via drill 0.61)
  Top 0.254: v40.64,34.29 36.83,30.48 IC6.22
  Bottom 0.254: 41.27,34.92 41.91,34.29 44.45,34.29 45.72,33.02 57.15,33.02 IC8.27 59.69,33.02 63.5,33.02 64.77,34.29 78.74,34.29 80.01,33.02 IC9.27 | 41.27,34.92 39.37,36.83 24.13,36.83 21.59,34.29 19.05,34.29 18.41,34.92 14.61,34.92 13.97,35.56 IC3.13 | 41.27,34.92 v40.64,34.29
A09  (via drill 0.61)
  Top 0.254: v31.75,31.75 34.92,28.57 IC6.21 36.83,27.94 v40.64,31.75
  Bottom 0.254: IC9.26 80.01,30.48 78.74,31.75 64.77,31.75 64.14,31.11 60.33,31.11 59.69,30.48 IC8.26 57.15,30.48 56.52,31.11 45.09,31.11 44.45,31.75 v40.64,31.75 | v31.75,31.75 19.05,31.75 17.78,33.02 13.97,33.02 IC3.12
A10  (via drill 0.61)
  Top 0.254: v22.23,36.83 22.23,17.14 20.95,15.88 IC6.9 | v50.16,15.88 57.15,22.86 IC8.23
  Bottom 0.254: IC8.23 59.69,22.86 60.33,23.5 64.14,23.5 64.77,24.13 76.2,24.13 77.47,22.86 80.01,22.86 IC9.23 | v22.23,36.83 20.95,38.1 13.97,38.1 IC3.14 | v50.16,15.88 49.53,16.51 22.86,16.51 21.59,15.24 IC6.9
A11  (via drill 0.61)
  Top 0.254: IC6.8 19.05,17.78 14.61,17.78 14.61,18.41 13.97,19.05 9.53,19.05 9.53,37.47 12.06,40.01 IC3.15 | v48.26,19.05 57.15,27.94 IC8.25
  Bottom 0.254: IC8.25 59.69,27.94 60.33,28.57 64.14,28.57 64.77,29.21 78.74,29.21 80.01,27.94 IC9.25 | v48.26,19.05 22.86,19.05 21.59,17.78 IC6.8
A12
  Top 0.254: IC8.4 42.55,38.73 40.64,40.64 40.64,52.7 IC4.9
  Bottom 0.254: IC9.4 64.77,38.1 63.5,36.83 45.72,36.83 44.45,38.1 IC8.4
A13  (via drill 0.61)
  Top 0.254: v49.53,51.44 55.88,45.09 55.88,38.1 57.78,36.2 IC8.28
  Bottom 0.254: IC8.28 59.69,35.56 60.33,36.2 64.14,36.2 64.77,36.83 77.47,36.83 78.74,35.56 80.01,35.56 IC9.28 | v49.53,51.44 38.73,51.44 34.29,55.88 IC4.7
A14  (via drill 0.61)
  Top 0.254: v42.55,54.61 42.55,47.62 41.27,46.35 41.27,42.55 42.55,41.27 IC8.3
  Bottom 0.254: IC8.3 44.45,40.64 45.72,39.37 63.5,39.37 64.77,40.64 IC9.3 | v42.55,54.61 38.1,54.61 34.29,58.42 IC4.6
A15  (via drill 0.61)
  Top 0.254: v64.14,44.45 64.14,48.26 66.04,50.16 J1.2
  Bottom 0.254: IC8.31 59.69,43.18 60.96,44.45 v64.14,44.45 78.74,44.45 80.01,43.18 IC9.31
A16  (via drill 0.61)
  Top 0.254: v77.47,54.61 66.67,43.81 IC9.2
  Bottom 0.254: IC8.2 44.45,43.18 45.72,41.91 63.5,41.91 64.77,43.18 IC9.2 | v77.47,54.61 116.84,54.61 118.11,53.34 IC7.9
A17  (via drill 0.61)
  Top 0.254: v83.19,21.59 83.19,38.73 81.92,40.01 IC9.30 | v89.53,52.07 85.09,47.62 v85.09,44.45
  Bottom 0.254: v83.19,21.59 64.77,21.59 64.14,20.95 60.33,20.95 59.69,20.32 IC8.22 | v89.53,52.07 121.28,52.07 121.28,53.98 120.65,54.61 118.11,54.61 117.47,55.24 113.67,55.24 113.03,55.88 IC7.7 | v85.09,44.45 81.92,41.27 IC9.30
BIT0\  (via drill 0.61)
  Top 0.254: v109.22,22.86 109.22,13.97 100.97,13.97 99.69,12.7 97.79,12.7 IC10.11
  Bottom 0.254: v109.22,22.86 110.49,24.13 120.65,24.13 121.92,22.86 125.73,22.86 IC5.15
BIT1\  (via drill 0.61)
  Top 0.254: v100.97,6.35 100.97,6.99 97.79,10.16 IC10.10 | v122.56,5.71 125.73,8.89 128.91,8.89 128.91,18.41 127.64,19.68 IC5.14
  Bottom 0.254: v100.97,6.35 101.6,5.71 v122.56,5.71
BIT2\  (via drill 0.61)
  Top 0.254: v100.97,12.7 100.97,11.43 95.25,11.43 94.61,10.79 94.61,9.53 95.89,8.26 IC10.9
  Bottom 0.254: v100.97,12.7 102.23,13.97 113.03,13.97 115.57,16.51 121.92,16.51 123.19,17.78 125.73,17.78 IC5.13
BIT3\
  Bottom 0.254: IC11.11 113.03,12.7 114.3,13.97 123.19,13.97 124.46,15.24 125.73,15.24 IC5.12
BIT4\
  Bottom 0.254: IC11.10 113.03,10.16 114.3,11.43 124.46,11.43 125.73,12.7 IC5.11
BIT5\
  Bottom 0.254: IC11.9 113.03,7.62 114.3,8.89 122.56,8.89 123.83,10.16 125.73,10.16 IC5.10
BIT6\  (via drill 0.61)
  Top 0.254: v99.69,46.35 99.69,38.73 97.16,36.2 IC12.11
  Bottom 0.254: v99.69,46.35 100.33,45.72 139.06,45.72 148.59,36.2 148.59,8.26 127.64,8.26 IC5.9
BIT7\  (via drill 0.61)
  Top 0.254: v99.06,16.51 99.06,19.05 99.69,19.68 99.69,29.84 97.16,32.38 IC12.10 | v113.67,16.51 117.47,12.7 117.47,12.06 118.75,10.79 IC5.7
  Bottom 0.254: v99.06,16.51 v113.67,16.51
BS0  (via drill 0.61)
  Top 0.254: IC1.9 13.97,7.62 19.05,12.7 IC6.10 | v132.72,6.99 140.34,14.61 140.34,15.88 141.6,17.14 IC14.11
  Bottom 0.254: IC5.1 120.65,25.4 121.92,24.13 138.43,24.13 140.97,21.59 143.51,21.59 144.15,20.95 144.15,18.41 142.88,18.41 IC14.11 | v132.72,6.99 127.64,1.91 3.17,1.91 3.17,5.71 3.81,6.35 10.16,6.35 11.43,7.62 IC1.9
BS1  (via drill 0.61)
  Top 0.254: v123.19,16.51 123.19,19.05 120.02,22.23 IC5.2 120.02,23.5 123.19,26.67 123.19,66.67 122.56,67.31 v122.56,94.61 | 22.23,13.97 11.43,13.97 10.16,12.7 10.16,3.81 3.81,3.81 3.17,4.45 3.17,5.71 4.45,6.99 IC1.6 | 22.23,13.97 22.23,12.06 20.95,10.79 IC6.11 | v23.5,87.63 22.86,87 22.86,37.47 23.5,36.83 23.5,15.24 22.23,13.97
  Bottom 0.254: v123.19,16.51 139.7,16.51 140.97,15.24 IC14.10 | v23.5,87.63 26.67,87.63 32.38,93.34 IC2.1 34.29,93.98 37.47,97.16 120.02,97.16 v122.56,94.61
BS2  (via drill 0.61)
  Top 0.254: v124.46,13.97 121.92,16.51 121.92,17.78 120.02,19.68 IC5.3 | IC2.2 32.38,90.81 31.11,89.53 31.11,60.33 30.48,59.69 30.48,15.24 34.92,10.79 IC6.14 | v130.81,2.54 140.97,12.7 IC14.9
  Bottom 0.254: v124.46,13.97 139.7,13.97 140.97,12.7 IC14.9 | 8.89,11.43 33.02,11.43 34.29,10.16 IC6.14 | 8.89,11.43 7.62,11.43 6.35,10.16 IC1.5 | v130.81,2.54 129.54,1.27 2.54,1.27 2.54,13.97 6.35,13.97 8.89,11.43
CLK  (via drill 0.61)
  Top 0.254: v9.53,50.16 3.17,43.81 3.17,22.23 4.45,20.95 IC1.1 | v84.45,59.05 83.19,60.33 83.19,61.59 81.92,62.87 IC22.5
  Bottom 0.254: v9.53,50.16 52.7,50.16 57.15,54.61 75.56,54.61 78.11,57.15 82.55,57.15 v84.45,59.05
D0  (via drill 0.61)
  Top 0.254: v100.33,19.05 100.33,30.48 104.14,34.29 IC13.2
  Bottom 0.254: IC14.13 142.88,23.5 144.78,25.4 144.78,33.66 106.05,33.66 104.78,34.92 IC13.2 | IC8.13 44.45,15.24 45.72,13.97 59.69,13.97 60.96,15.24 64.77,15.24 IC9.13 67.31,15.24 78.74,15.24 80.01,13.97 92.71,13.97 95.89,17.14 IC10.13 97.79,17.78 99.06,17.78 v100.33,19.05
D1  (via drill 0.61)
  Top 0.254: v111.76,27.3 111.76,34.29 IC13.5 | v77.47,24.13 66.67,13.34 IC9.14
  Bottom 0.254: IC8.14 44.45,12.7 45.72,11.43 59.69,11.43 60.96,12.7 64.77,12.7 IC9.14 | 111.76,26.67 139.7,26.67 140.97,25.4 IC14.14 | 111.76,26.67 91.44,26.67 90.17,25.4 IC10.1 87.63,25.4 86.36,24.13 v77.47,24.13 | 111.76,26.67 v111.76,27.3
D2  (via drill 0.61)
  Top 0.254: v85.72,20.32 86.36,19.68 86.36,10.16 87.63,8.89 90.81,8.89 90.81,6.99 90.17,6.35 | 90.17,6.35 67.94,6.35 67.94,8.26 66.67,9.53 IC9.15 | 90.17,6.35 90.17,1.27 133.35,1.27 144.15,12.06 144.15,26.04 142.88,27.3 IC14.15 | v114.3,32.38 114.3,34.29 IC13.6
  Bottom 0.254: IC8.15 44.45,10.16 45.72,8.89 59.69,8.89 60.96,10.16 64.77,10.16 IC9.15 | v85.72,20.32 87.63,20.32 IC10.3 | v114.3,32.38 114.94,31.75 143.51,31.75 144.15,31.11 144.15,28.57 142.88,28.57 IC14.15
D3  (via drill 0.61)
  Top 0.254: IC13.9 121.92,34.29 121.92,29.21 119.38,26.67 117.47,26.67 117.47,18.41 116.84,17.78 113.03,17.78 IC11.13 111.12,17.14 109.86,15.88 109.86,5.71 v107.31,3.17
  Bottom 0.254: IC8.17 59.69,7.62 60.96,8.89 78.74,8.89 80.01,7.62 IC9.17 82.55,7.62 87,3.17 v107.31,3.17 | IC11.13 113.03,17.78 114.3,19.05 139.7,19.05 140.97,20.32 IC14.12
D4  (via drill 0.61)
  Top 0.254: v105.41,29.21 105.41,26.67 104.78,26.04 IC11.1 103.5,24.77 101.6,22.86 101.6,17.14 v98.42,13.97 | v120.65,29.21 120.65,40.64 121.92,41.91 IC13.12
  Bottom 0.254: IC8.18 59.69,10.16 60.96,11.43 78.74,11.43 80.01,10.16 IC9.18 82.55,10.16 83.82,11.43 90.17,11.43 92.08,13.34 94.61,13.34 95.25,13.97 v98.42,13.97 | v105.41,29.21 v120.65,29.21 132.08,29.21 133.35,30.48 IC14.1
D5  (via drill 0.61)
  Top 0.254: v115.57,21.59 115.57,40.64 114.3,41.91 IC13.15 | v83.19,19.05 83.19,14.61 81.92,13.34 IC9.19
  Bottom 0.254: IC8.19 59.69,12.7 60.96,13.97 78.74,13.97 80.01,12.7 IC9.19 | IC14.5 133.35,20.32 132.08,21.59 v115.57,21.59 110.49,21.59 109.22,20.32 105.41,20.32 IC11.3 102.87,20.32 100.33,20.32 99.06,19.05 v83.19,19.05
D6  (via drill 0.61)
  Top 0.254: v132.72,40.64 132.72,29.84 133.99,28.57 IC14.2 | v93.34,16.51 94.61,17.78 94.61,38.73 95.89,40.01 IC12.13
  Bottom 0.254: IC8.20 59.69,15.24 60.33,15.88 64.14,15.88 64.77,16.51 78.74,16.51 80.01,15.24 IC9.20 82.55,15.24 83.82,16.51 v93.34,16.51 | 109.86,41.27 111.12,42.55 IC13.16 | 109.86,41.27 109.22,40.64 97.79,40.64 IC12.13 | v132.72,40.64 132.08,41.27 109.86,41.27
D7  (via drill 0.61)
  Top 0.254: v99.69,49.53 104.14,45.09 104.14,44.45 IC13.19 | v131.44,46.99 131.44,40.64 132.08,40.01 132.08,25.4 133.99,23.5 IC14.4 | v79.38,46.99 79.38,19.68 80.64,18.41 IC9.21
  Bottom 0.254: IC8.21 59.69,17.78 60.33,18.41 64.14,18.41 64.77,19.05 78.74,19.05 80.01,17.78 IC9.21 | v131.44,46.99 128.91,49.53 v99.69,49.53 91.44,49.53 90.17,48.26 IC12.1 87.63,48.26 80.64,48.26 v79.38,46.99
DMP
  Bottom 0.254: IC19.8 64.77,76.2 63.5,74.93 52.7,74.93 51.44,76.2 SV09.16
DMP_S  (via drill 0.61)
  Top 0.254: v128.27,74.93 135.25,67.94 135.25,32.38 136.53,31.11 136.53,27.3 135.25,26.04 IC14.3
  Bottom 0.254: v128.27,74.93 71.12,74.93 67.31,78.74 IC19.9
EM0
  Bottom 0.254: IC20.2 110.49,91.44 107.95,88.9 104.78,88.9 SV11.6
EM0_S
  Top 0.254: IC7.10 120.02,56.52 121.92,58.42 121.92,93.98 120.65,95.25 112.39,95.25 112.39,94.61 IC20.1
EM1
  Top 0.254: IC20.6 110.49,81.28 105.41,86.36 104.78,86.36 SV11.8
EM1_S
  Top 0.254: IC7.11 118.75,59.05 113.67,64.14 113.67,74.93 112.39,76.2 112.39,78.11 IC20.7
EM2
  Bottom 0.254: IC20.9 118.11,81.28 116.84,82.55 106.05,82.55 104.78,81.28 SV11.12
EM2_S
  Top 0.254: IC7.12 118.75,61.59 117.47,62.87 117.47,76.83 118.75,78.11 IC20.8
EM3
  Bottom 0.254: IC20.13 120.02,90.81 121.28,89.53 121.28,77.47 106.05,77.47 104.78,76.2 SV11.16
EM3_S
  Top 0.254: IC7.13 120.02,64.14 121.28,65.41 121.28,92.08 120.02,93.34 IC20.14
EMA3  (via drill 0.61)
  Top 0.254: v56.52,71.12 56.52,57.78 57.78,56.52 IC18.6
  Bottom 0.254: v56.52,71.12 57.78,72.39 102.23,72.39 103.5,71.12 SV11.20
EMA3_S
  Top 0.254: IC18.7 57.78,52.7 56.52,51.44 56.52,50.8 J1.1
GND  (via drill 0.61)
  Top 0.381: SV10.34 6.99,53.34 5.71,53.34 SV10.33 5.08,53.98 5.08,55.24 SV10.31 5.08,56.52 5.08,57.78 SV10.29 5.08,59.05 5.08,60.33 SV10.27 5.08,61.59 5.08,62.87 SV10.25 | SV10.25 5.08,64.14 5.08,65.41 SV10.23 5.08,66.67 5.08,67.94 SV10.21 | SV10.22 6.99,68.58 5.71,68.58 SV10.21 | SV10.21 5.08,69.22 5.08,70.48 SV10.19 5.08,71.75 5.08,73.03 SV10.17 | SV10.18 6.99,73.66 5.71,73.66 SV10.17 | SV10.17 5.08,74.3 5.08,75.56 SV10.15 5.08,76.83 5.08,78.11 SV10.13 | SV10.14 6.99,78.74 5.71,78.74 SV10.13 | SV10.13 5.08,79.38 5.08,80.64 SV10.11 5.08,81.92 5.08,83.19 SV10.9 | SV10.9 5.08,84.45 5.08,85.72 SV10.7 5.08,87 5.08,88.27 SV10.5 5.08,89.53 5.08,90.81 SV10.3 5.08,92.08 5.08,93.34 SV10.1 | SV10.26 6.99,63.5 5.71,63.5 SV10.25 | SV10.10 6.99,83.82 5.71,83.82 SV10.9 | IC6.15 34.92,13.34 34.92,14.61 IC6.16 34.92,15.88 34.92,17.14 IC6.17 34.92,18.41 34.92,19.68 IC6.18 34.92,20.95 34.92,22.23 IC6.19 34.92,23.5 34.92,24.77 IC6.20 | SV09.33 48.9,53.34 50.16,53.34 SV09.34 | SV09.33 48.26,53.98 48.26,55.24 SV09.31 48.26,56.52 48.26,57.78 SV09.29 48.26,59.05 48.26,60.33 SV09.27 48.26,61.59 48.26,62.87 SV09.25 48.26,64.14 48.26,65.41 SV09.23 48.26,66.67 48.26,67.94 SV09.21 48.26,69.22 48.26,70.48 SV09.19 48.26,71.75 48.26,73.03 SV09.17 | SV09.18 50.16,73.66 48.9,73.66 SV09.17 | SV09.17 48.26,74.3 48.26,75.56 SV09.15 48.26,76.83 48.26,78.11 SV09.13 | SV09.14 50.16,78.74 48.9,78.74 SV09.13 | SV09.13 48.26,79.38 48.26,80.64 SV09.11 48.26,81.92 48.26,83.19 SV09.9 | SV09.9 48.26,84.45 48.26,85.72 SV09.7 48.26,87 48.26,88.27 SV09.5 48.26,89.53 48.26,90.81 SV09.3 48.26,92.08 48.26,93.34 SV09.1
  Top 0.381: SV09.10 50.16,83.82 48.9,83.82 SV09.9 | v48.26,24.13 48.26,52.7 SV09.33 | 84.45,20.32 82.55,20.32 IC9.22 | 84.45,20.32 84.45,10.79 87.63,7.62 IC10.8 | 84.45,20.32 v84.45,26.04 83.82,26.67 83.82,52.7 C1.2 83.82,53.98 83.82,57.15 82.55,58.42 IC22.7 | J4.1 124.46,48.9 124.46,50.16 J3.1 | IC13.10 124.46,36.83 128.91,41.27 128.91,52.7 IC17.8 | 100.97,92.71 92.71,92.71 IC21.2 | 100.97,92.71 100.97,93.98 SV11.1 | 100.97,92.71 101.6,92.08 SV11.3 101.6,90.81 101.6,89.53 SV11.5 101.6,88.27 101.6,87 SV11.7 101.6,85.72 101.6,84.45 SV11.9 | IC7.4 111.12,64.14 111.12,65.41 IC7.3 111.12,66.67 111.12,67.94 IC7.2 | IC7.1 111.12,70.48 111.12,69.22 IC7.2 | C2.2 75.56,60.96 71.75,60.96 C3.2 | C4.2 83.82,80.64 83.82,82.55 D3.C 83.19,84.45 83.19,90.81 81.28,92.71 D6.A | SV11.34 103.5,53.34 102.23,53.34 SV11.33 101.6,53.98 101.6,55.24 SV11.31 101.6,56.52 101.6,57.78 SV11.29 101.6,59.05 101.6,60.33 SV11.27 101.6,61.59 101.6,62.87 SV11.25 | SV11.26 103.5,63.5 102.23,63.5 SV11.25 | SV11.25 101.6,64.14 101.6,65.41 SV11.23 101.6,66.67 101.6,67.94 SV11.21 | SV11.21 102.23,68.58 103.5,68.58 SV11.22 104.78,68.58 110.49,68.58 IC7.2 | SV11.21 101.6,69.22 101.6,70.48 SV11.19 101.6,71.75 101.6,73.03 SV11.17 | SV11.17 101.6,74.3 101.6,75.56 SV11.15 101.6,76.83 101.6,78.11 SV11.13 | SV11.18 103.5,73.66 102.23,73.66 SV11.17 | SV11.14 103.5,78.74 102.23,78.74 SV11.13 | SV11.13 101.6,79.38 101.6,80.64 SV11.11 101.6,81.92 101.6,83.19 SV11.9 | SV11.10 103.5,83.82 102.23,83.82 SV11.9
  Bottom 0.381: SV10.10 8.26,83.82 9.53,85.09 22.86,85.09 24.13,86.36 IC15.11 26.67,86.36 27.94,85.09 46.35,85.09 47.62,86.36 SV09.7 | SV10.26 8.26,63.5 9.53,62.23 22.86,62.23 24.13,60.96 IC16.11 26.67,60.96 27.94,62.23 63.5,62.23 64.77,60.96 IC18.11 67.31,60.96 70.48,60.96 C3.2 | IC19.4 57.15,83.82 51.44,83.82 SV09.10 | SV09.26 50.16,63.5 48.9,63.5 SV09.25 | SV09.22 50.16,68.58 48.9,68.58 SV09.21 | v48.26,24.13 41.91,24.13 41.27,24.77 37.47,24.77 36.83,25.4 IC6.20 | v84.45,26.04 88.27,29.84 IC12.8 | IC14.8 133.35,12.7 129.54,8.89 123.83,8.89 122.56,7.62 120.65,7.62 IC5.8 118.11,7.62 116.84,6.35 106.68,6.35 105.41,7.62 IC11.8 102.87,7.62 100.33,7.62 99.06,6.35 91.44,6.35 90.17,7.62 IC10.8 | J2.1 146.69,35.56 145.41,36.83 124.46,36.83 IC13.10 | J3.1 125.09,50.8 127.64,53.34 128.27,53.34 IC17.8 130.18,53.98 131.44,55.24 131.44,70.48 130.18,70.48 IC17.1 128.27,71.12 127,72.39 114.3,72.39 113.03,71.12 IC7.1 | IC20.11 118.75,87 113.03,92.71 103.5,92.71 102.23,93.98 SV11.1 | IC22.7 80.01,58.42 77.47,60.96 76.83,60.96 C2.2 | C4.2 84.45,80.01 85.72,81.28 100.97,81.28 SV11.11 | C1.2 84.45,53.34 100.97,53.34 SV11.33
LI0  (via drill 0.61)
  Top 0.254: v106.05,21.59 106.68,22.23 106.68,34.29 IC13.3
  Bottom 0.254: v106.05,21.59 99.06,21.59 97.79,20.32 IC10.14
LI1  (via drill 0.61)
  Top 0.254: v98.42,27.94 98.42,24.77 97.16,23.5 IC10.15 | v107.95,27.94 109.22,29.21 109.22,34.29 IC13.4
  Bottom 0.254: v98.42,27.94 v107.95,27.94
LI2  (via drill 0.61)
  Top 0.254: v91.44,33.66 91.44,20.32 89.53,18.41 IC10.4
  Bottom 0.254: v91.44,33.66 92.08,34.29 100.33,34.29 100.97,33.66 102.23,33.66 102.87,34.29 102.87,36.83 103.5,37.47 114.94,37.47 116.2,36.2 IC13.7
LI3  (via drill 0.61)
  Top 0.254: v114.3,30.48 114.3,22.86 112.39,20.95 IC11.14 | v118.11,30.48 119.38,31.75 119.38,34.29 IC13.8
  Bottom 0.254: v114.3,30.48 v118.11,30.48
LI4
  Top 0.254: IC11.15 111.12,22.23 109.86,20.95 109.86,19.68 110.49,19.05 116.84,19.05 116.84,33.02 118.11,34.29 118.11,40.64 119.38,41.91 IC13.13
LI5
  Top 0.254: IC11.4 104.78,18.41 107.95,21.59 107.95,22.86 109.22,24.13 113.67,24.13 113.67,29.84 113.03,30.48 113.03,44.45 113.67,45.09 116.84,45.09 116.84,44.45 IC13.14
LI6
  Bottom 0.254: IC12.14 97.79,43.18 99.69,41.27 107.31,41.27 108.58,42.55 IC13.17
LI7
  Bottom 0.254: IC12.15 97.79,45.72 98.42,45.09 104.78,45.09 106.05,43.81 IC13.18
N$1
  Bottom 0.254: IC3.10 12.06,28.57 6.99,28.57 6.35,29.21 3.17,29.21 3.17,27.3 3.81,26.67 6.35,26.67 9.53,23.5 14.61,23.5 14.61,14.61 13.97,13.97 10.16,13.97 6.35,17.78 IC1.2 4.45,18.41 1.27,18.41 1.27,75.56 3.17,77.47 8.26,77.47 10.79,80.01 38.1,80.01 39.37,81.28 IC2.9
N$2
  Top 0.254: D2.C 76.2,85.09 73.66,87.63 73.66,92.71 D1.A
N$3
  Top 0.254: D4.C 86.36,85.09 83.82,87.63 83.82,92.71 D3.A
N$5
  Top 0.254: D6.C 81.28,85.09 78.74,87.63 78.74,92.71 D5.A
N$6
  Top 0.254: C1.1 78.74,53.98 78.74,55.24 R4.1 78.74,56.52 78.74,58.42 79.38,59.05 | 79.38,59.05 80.64,60.33 IC22.6 | 79.38,59.05 79.38,69.22 80.64,70.48 IC22.2
N$7
  Bottom 0.254: C2.1 75.56,66.04 74.3,64.77 70.48,64.77 69.85,65.41 69.85,68.58 80.01,68.58 IC22.3
N$8
  Top 0.254: IC22.12 88.27,69.22 88.27,70.48 IC22.13 88.27,71.75 87,73.03 87,74.93 88.27,76.2 R3.1 88.9,76.83 88.9,79.38 C4.1
N$10
  Bottom 0.254: C3.1 71.75,66.04 73.03,67.31 86.36,67.31 87.63,66.04 IC22.11
PHASE
  Bottom 0.254: IC1.12 12.06,15.88 1.91,26.04 1.91,74.93 36.2,74.93 38.1,73.03 46.99,73.03 47.62,72.39 53.98,72.39 56.52,69.85 127,69.85 128.27,68.58 IC17.2
PSM_P
  Bottom 0.254: IC3.11 11.43,30.48 10.79,31.11 6.99,31.11 6.35,31.75 3.81,31.75 2.54,33.02 2.54,43.18 3.81,43.18 IC3.1 4.45,43.81 3.81,43.81 3.81,71.75 4.45,72.39 41.91,72.39 44.45,69.85 51.44,69.85 56.52,64.77 67.31,64.77 69.85,62.23 83.82,62.23 87.63,58.42 IC22.8
PSM_S  (via drill 0.61)
  Top 0.254: IC2.5 32.38,84.45 32.38,85.72 IC2.4 32.38,87 32.38,88.27 IC2.3 | v83.82,76.2 83.82,66.04 88.27,61.59 IC22.9
  Bottom 0.254: v83.82,76.2 80.01,80.01 44.45,80.01 41.91,82.55 35.56,82.55 34.29,83.82 IC2.5
PSM_S\  (via drill 0.61)
  Top 0.254: v34.92,87.63 34.92,83.19 33.66,81.92 IC2.6 | IC22.4 81.92,66.67 83.19,67.94 83.19,74.3 74.93,82.55 74.93,85.09 71.12,88.9 67.31,88.9 IC19.13
  Bottom 0.254: v34.92,87.63 63.5,87.63 64.77,88.9 IC19.13
T2\  (via drill 0.61)
  Top 0.254: IC5.4 118.75,17.14 118.75,15.88 IC5.5 120.02,14.61 121.28,13.34 121.28,6.99 120.65,6.35 120.65,3.17 125.09,3.17 131.44,9.53 131.44,27.94 130.18,29.21 130.18,46.99 131.44,48.26 131.44,61.59 130.18,62.87 IC17.4 | v76.83,27.94 76.83,49.53 82.55,55.24 v82.55,55.88
  Bottom 0.254: 76.83,26.67 78.74,26.67 80.01,25.4 IC9.24 | 76.83,26.67 64.77,26.67 64.14,26.04 60.33,26.04 59.69,25.4 IC8.24 | 76.83,26.67 v76.83,27.94 | v82.55,55.88 83.82,57.15 93.98,57.15 96.52,59.69 124.46,59.69 128.27,63.5 IC17.4
T4\  (via drill 0.61)
  Top 0.254: v95.25,57.15 91.44,53.34 v91.44,40.64
  Bottom 0.254: 78.74,39.37 64.77,39.37 64.14,38.73 60.33,38.73 59.69,38.1 IC8.29 | 78.74,39.37 80.01,38.1 IC9.29 | v95.25,57.15 127,57.15 128.27,58.42 IC17.6 | v91.44,40.64 90.17,39.37 78.74,39.37
TTA
  Bottom 0.254: IC19.1 57.15,91.44 54.61,88.9 51.44,88.9 SV09.6
TTA_S  (via drill 0.61)
  Top 0.254: v127.64,42.55 127.64,64.14 128.91,65.41 IC17.3 128.91,66.67 125.73,69.85 125.73,92.71 121.92,96.52 56.52,96.52 56.52,95.25 | 56.52,95.25 47.62,95.25 46.99,94.61 46.99,52.7 47.62,52.07 47.62,48.9 46.99,48.26 46.99,6.35 11.43,6.35 10.79,6.99 10.79,10.79 12.06,12.06 IC1.11 | 56.52,95.25 56.52,90.81 57.78,89.53 IC19.2
  Bottom 0.254: 127.64,41.91 124.46,41.91 IC13.11 | 127.64,41.91 133.99,41.91 133.99,40.64 132.72,39.37 104.14,39.37 101.6,36.83 IC13.1 | v127.64,42.55 127.64,41.91
TTB
  Top 0.254: IC19.7 57.78,76.83 52.07,82.55 52.07,84.45 50.8,85.72 SV09.8
TTB_S  (via drill 0.61)
  Top 0.254: v20.95,76.2 20.95,36.2 IC6.1
  Bottom 0.254: v20.95,76.2 21.59,75.56 36.83,75.56 37.47,74.93 45.09,74.93 47.62,77.47 55.88,77.47 57.15,78.74 IC19.6
VCC  (via drill 0.61)
  Top 0.381: v130.18,27.94 130.18,27.3 128.27,25.4 IC5.16 | IC20.4 112.39,85.72 114.3,83.82 114.3,76.83 J5.1 | IC14.16 141.6,31.11 139.06,33.66 139.06,69.22 137.79,70.48 IC17.16 | IC22.1 80.01,73.66 78.74,74.93 78.74,75.56 R3.2 | IC21.1 93.98,90.81 90.17,87 90.17,73.66 IC22.14 89.53,73.03 90.81,71.75 90.81,61.59 | IC16.4 18.41,61.59 19.68,62.87 19.68,84.45 18.41,85.72 IC15.4 | IC8.30 57.78,41.27 56.52,42.55 56.52,43.81 57.78,45.09 IC8.32 59.05,46.35 60.33,47.62 60.33,59.05 59.05,60.33 IC18.4 | 90.81,58.42 90.81,61.59 | 90.81,58.42 90.81,57.15 89.53,55.88 R4.2 | 90.81,61.59 89.53,62.87 IC22.10 | 90.81,58.42 96.52,58.42 96.52,48.9 IC12.16 | IC11.16 111.12,26.04 110.49,26.67 110.49,36.83 106.05,41.27 101.6,41.27 101.6,41.91 IC13.20
  Bottom 0.381: v130.18,27.94 130.81,28.57 132.72,28.57 133.35,29.21 139.7,29.21 140.97,30.48 IC14.16 | IC17.16 135.89,71.12 129.54,77.47 122.56,77.47 121.28,76.2 114.94,76.2 J5.1 | IC22.14 87.63,73.66 82.55,73.66 IC22.1 | IC10.16 97.79,25.4 98.42,24.77 102.23,24.77 102.87,24.13 109.22,24.13 110.49,25.4 IC11.16 | 92.71,46.99 93.98,46.99 95.25,48.26 IC12.16 | 92.71,46.99 83.82,46.99 82.55,45.72 IC9.32 80.01,45.72 78.74,45.72 77.47,46.99 60.96,46.99 59.69,45.72 IC8.32 | 92.71,46.99 95.25,44.45 100.33,44.45 100.97,43.81 IC13.20 | IC16.4 19.05,60.96 20.32,59.69 53.98,59.69 55.24,60.96 57.15,60.96 IC18.4 | IC20.4 110.49,86.36 109.22,87.63 98.42,87.63 94.61,91.44 IC21.1
VDD  (via drill 0.61)
  Top 0.381: v123.83,67.31 124.46,67.94 v124.46,71.12 124.46,75.56 J5.2 124.46,76.83 123.83,77.47 v123.83,89.53 | IC4.16 41.27,71.75 42.55,73.03 42.55,92.08 41.27,93.34 IC2.14 | IC1.14 13.34,20.95 14.61,22.23 14.61,41.27 13.34,42.55 IC3.16 | 31.11,43.18 31.11,40.01 34.92,36.2 IC6.24 36.2,36.2 v36.2,66.67 | 31.11,43.18 31.11,59.05 32.38,60.33 IC4.5 | v31.75,43.18 31.11,43.18
  Bottom 0.381: v123.83,67.31 118.11,67.31 112.39,61.59 IC7.5 | v124.46,71.12 120.65,71.12 IC7.16 | v31.75,43.18 13.97,43.18 IC3.16 | v36.2,66.67 40.01,70.48 IC4.16 | v123.83,89.53 120.65,92.71 115.57,92.71 111.76,96.52 44.45,96.52 41.91,93.98 IC2.14
VEE
  Top 0.254: J2.2 137.16,34.92 137.16,20.32 135.25,18.41 IC14.6 133.99,17.14 133.99,15.88 IC14.7 133.99,14.61 132.08,12.7 132.08,8.89 125.09,1.91 106.05,1.91 106.05,8.26 104.78,9.53 IC11.7 103.5,10.79 103.5,12.06 IC11.6 | IC10.7 88.27,10.79 88.27,12.06 IC10.6 88.27,13.34 87,14.61 87,40.01 | IC12.7 88.27,33.66 88.27,34.92 IC12.6 88.27,36.2 88.27,37.47 IC12.5 88.27,38.73 87,40.01 | 87,40.01 87,41.27 88.27,42.55 IC12.3
  Bottom 0.254: IC10.7 90.17,10.16 91.44,11.43 101.6,11.43 102.87,12.7 IC11.6 | IC12.9 95.25,30.48 93.34,32.38 89.53,32.38 IC12.7
VSS  (via drill 0.61)
  Top 0.381: IC1.7 5.71,5.71 6.99,6.99 6.99,23.5 5.71,24.77 IC3.8 | IC7.8 112.39,52.7 113.67,51.44 113.67,50.8 J3.2 | IC2.7 33.66,78.11 34.92,76.83 34.92,55.24 33.66,53.98 IC4.8 33.66,52.7 33.66,50.16 v34.92,48.9 | v46.35,48.9 46.35,10.79 43.81,8.26 IC8.16
  Bottom 0.381: 17.78,6.35 19.05,7.62 IC6.12 | 17.78,6.35 11.43,6.35 10.16,5.08 6.35,5.08 IC1.7 | 40.64,6.35 41.91,7.62 IC8.16 | 17.78,6.35 40.64,6.35 | 40.64,6.35 63.5,6.35 64.77,7.62 IC9.16 | v34.92,48.9 v46.35,48.9 66.04,48.9 67.94,50.8 113.67,50.8 J3.2
WFF  (via drill 0.61)
  Top 0.254: v55.88,57.15 52.07,60.96 52.07,64.14 50.8,65.41 SV09.24
  Bottom 0.254: v55.88,57.15 63.5,57.15 64.77,55.88 IC18.9
WFF_S  (via drill 0.61)
  Top 0.254: 92.08,15.24 95.25,15.24 IC10.12 | 92.08,15.24 90.17,15.24 IC10.5 | IC11.2 103.5,22.23 102.23,20.95 102.23,17.14 103.5,15.88 IC11.5 | v85.09,52.07 86.36,53.34 90.81,53.34 90.81,47.62 89.53,46.35 IC12.2 | 92.08,15.24 92.08,33.02 93.98,34.92 93.98,40.64 95.25,41.91 98.42,41.91 98.42,40.01 97.16,38.73 IC12.12
  Bottom 0.254: IC10.2 90.17,22.86 91.44,24.13 101.6,24.13 102.87,22.86 IC11.2 | IC10.12 97.79,15.24 102.87,15.24 IC11.5 105.41,15.24 110.49,15.24 IC11.12 | IC12.2 89.53,45.09 95.89,38.73 IC12.12 | v85.09,52.07 68.58,52.07 67.31,53.34 IC18.8
WLO
  Top 0.254: SV11.28 104.14,60.33 109.86,54.61 109.86,52.07 113.67,48.26 J4.2
WTE
  Bottom 0.254: IC18.2 57.15,66.04 52.07,71.12 51.44,71.12 SV09.20
WTE_S  (via drill 0.61)
  Top 0.254: v78.74,10.16 78.74,11.43 64.77,11.43 60.96,15.24 60.96,66.04 59.05,67.94 IC18.1
  Bottom 0.254: v78.74,10.16 80.01,8.89 107.95,8.89 110.49,11.43 113.03,11.43 114.3,12.7 118.11,12.7 IC5.6
X0
  Bottom 0.254: IC15.2 16.51,91.44 13.97,88.9 8.26,88.9 SV10.6
X0_S
  Top 0.254: IC4.10 40.01,56.52 37.47,59.05 37.47,74.93 36.2,76.2 36.2,90.81 34.29,92.71 18.41,92.71 18.41,93.34 IC15.1
X1
  Bottom 0.254: IC15.6 16.51,81.28 15.88,80.64 8.89,80.64 8.26,80.01 4.45,80.01 3.81,80.64 3.81,85.09 5.71,85.09 6.99,86.36 SV10.8
X1_S  (via drill 0.61)
  Top 0.254: v37.47,76.2 38.1,75.56 38.1,60.96 40.01,59.05 IC4.11
  Bottom 0.254: v37.47,76.2 27.94,76.2 26.67,77.47 20.32,77.47 19.05,78.74 IC15.7
X2
  Bottom 0.254: IC15.9 24.13,81.28 22.86,82.55 9.53,82.55 8.26,81.28 SV10.12
X2_S  (via drill 0.61)
  Top 0.254: v38.73,76.2 38.73,62.87 40.01,61.59 IC4.12
  Bottom 0.254: v38.73,76.2 37.47,77.47 27.94,77.47 26.67,78.74 IC15.8
X3
  Top 0.254: IC15.13 24.13,91.44 19.68,91.44 19.68,88.27 19.05,87.63 8.89,87.63 8.89,78.11 7.62,76.83 SV10.16
X3_S
  Top 0.254: IC4.13 41.27,64.14 43.18,66.04 43.18,93.98 41.91,95.25 26.04,95.25 26.04,94.61 IC15.14
X4
  Bottom 0.254: IC16.2 16.51,66.04 11.43,71.12 8.26,71.12 SV10.20
X4_S
  Bottom 0.254: IC16.1 19.05,68.58 21.59,71.12 31.75,71.12 IC4.1
X5
  Top 0.254: IC16.6 17.14,56.52 8.26,65.41 8.26,66.04 SV10.24
X5_S  (via drill 0.61)
  Top 0.254: v15.24,68.58 15.24,59.69 19.05,59.69 19.68,59.05 19.68,55.24 18.41,53.98 IC16.7
  Bottom 0.254: v15.24,68.58 16.51,67.31 30.48,67.31 31.75,68.58 IC4.2
X6
  Bottom 0.254: IC16.9 24.13,55.88 22.86,57.15 12.06,57.15 8.26,60.96 SV10.28
X6_S  (via drill 0.61)
  Top 0.254: v29.84,66.04 29.84,56.52 26.67,53.34 IC16.8
  Bottom 0.254: v29.84,66.04 31.75,66.04 IC4.3
X7
  Bottom 0.254: IC16.13 24.13,66.04 22.86,64.77 6.99,64.77 6.35,64.14 6.35,59.05 7.62,59.05 SV10.30
X7_S  (via drill 0.61)
  Top 0.254: v28.57,63.5 28.57,57.15 24.13,57.15 23.5,57.78 23.5,66.67 24.77,67.94 IC16.14
  Bottom 0.254: v28.57,63.5 31.75,63.5 IC4.4
~NEX  (via drill 0.61)
  Top 0.254: v56.52,72.39 50.16,72.39 49.53,71.75 49.53,62.87 50.8,61.59 SV09.28
  Bottom 0.254: v56.52,72.39 57.78,73.66 65.41,73.66 J6.2
~PSM  (via drill 0.61)
  Top 0.254: v64.14,59.69 64.14,89.53 65.41,90.81 IC19.14
  Bottom 0.254: v64.14,59.69 55.24,59.69 53.98,58.42 51.44,58.42 SV09.30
